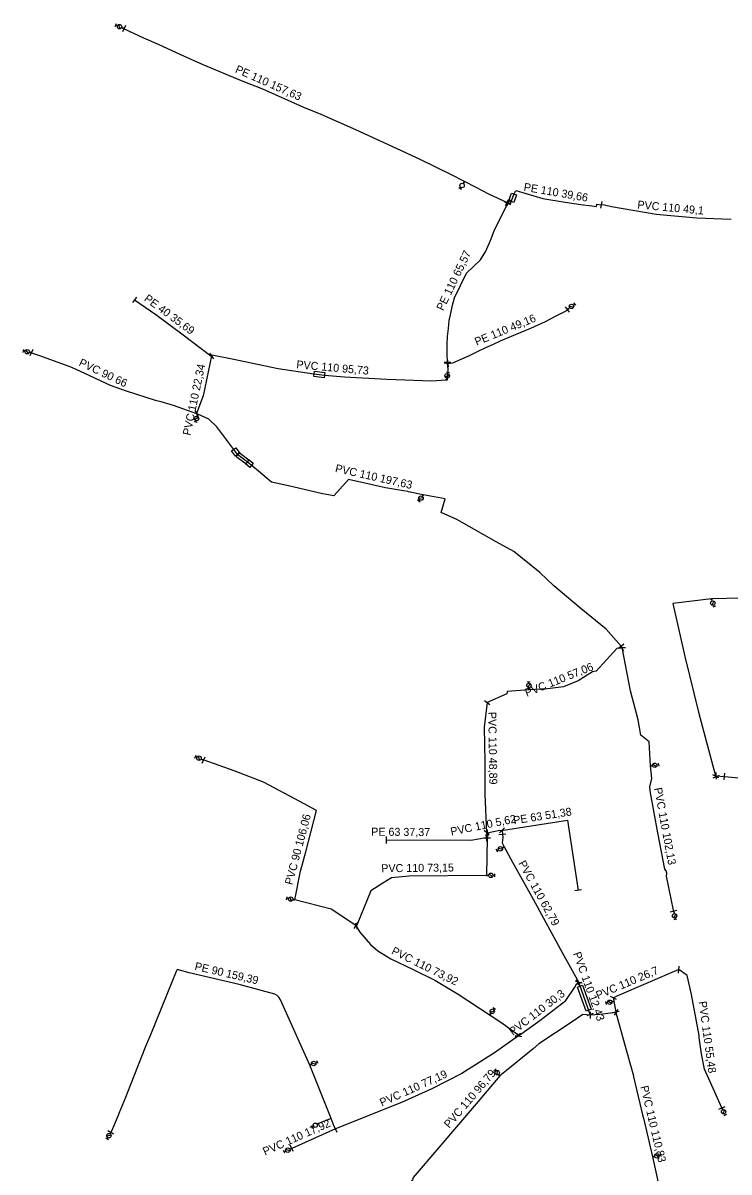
# Model space of a CAD drawing. Extents: x -736619 to -735426, y -1033122 to -1031044.
# Drawn here: x -736349.9 to -736085.4, y -1032291.7 to -1031861 of the extents above; entities that cross this region are included whole.
import ezdxf

# ---------------------------------------------------------------- set-up
doc = ezdxf.new("R2010")
doc.units = 0
for name, color, linetype in [('Vrstva 1', 7, 'Continuous'), ('Vrstva 17', 7, 'Continuous'), ('Vrstva 25', 7, 'Continuous'), ('Vrstva 27', 7, 'Continuous'), ('Vrstva 29', 7, 'Continuous'), ('Vrstva 63', 7, 'Continuous')]:
    doc.layers.add(name, color=color, linetype=linetype)

# ---------------------------------------------------------------- blocks, each defined once
blk = doc.blocks.new('100')
at = {"layer": 'Vrstva 1'}
blk.add_circle((0, 0), 0.127, dxfattribs=at)
blk = doc.blocks.new('133')
at = {"layer": 'Vrstva 1'}
for p, q in [((0.28, 0), (0, 0)), ((0.54, 0.58), (1.7, -0.58)), ((1.94, 0), (2.52, 0)), ((2.52, 0.58), (2.52, -0.58))]:
    blk.add_line(p, q, dxfattribs=at)
blk.add_circle((1.105, 0.003), 0.825, dxfattribs=at)
blk = doc.blocks.new('132')
at = {"layer": 'Vrstva 1'}
for p, q in [((0.3, 0), (0, 0)), ((1.96, 0), (2.52, 0)), ((2.52, 0.58), (2.52, -0.58))]:
    blk.add_line(p, q, dxfattribs=at)
blk.add_circle((1.13, -0.006), 0.825, dxfattribs=at)
blk = doc.blocks.new('147')
at = {"layer": 'Vrstva 1'}
blk.add_line((0, 1.27), (0, -1.27), dxfattribs=at)

msp = doc.modelspace()

# ---------------------------------------------------------------- linework, layer by layer
at = {"layer": 'Vrstva 17'}
for p, q in [((-736168.322, -1031928.384), (-736168.615, -1031928.284)), ((-736168.42, -1031928.571), (-736168.322, -1031928.384)), ((-736168.322, -1031928.384), (-736168.06, -1031928.485)), ((-736190.9, -1031988.615), (-736190.904, -1031988.283)), ((-736125.42, -1032095.1), (-736125.8, -1032094.64)), ((-736125.42, -1032095.1), (-736125.6, -1032095.31)), ((-736090.451, -1032143.226), (-736090.169, -1032143.164)), ((-736090.451, -1032143.226), (-736090.281, -1032143.568)), ((-736090.169, -1032143.164), (-736087.139, -1032143.448)), ((-736176.051, -1032166.446), (-736176.424, -1032166.463)), ((-736176.226, -1032164.522), (-736175.959, -1032164.508)), ((-736176.226, -1032164.522), (-736176.051, -1032166.446)), ((-736170.433, -1032163.629), (-736170.327, -1032165.199)), ((-736225.06, -1032199.49), (-736225.267, -1032199.35)), ((-736141.952, -1032220.805), (-736141.7, -1032220.64)), ((-736141.599, -1032220.922), (-736141.7, -1032220.64)), ((-736137.401, -1032232.618), (-736141.599, -1032220.922)), ((-736127.804, -1032231.644), (-736127.76, -1032231.89)), ((-736137.401, -1032232.618), (-736137.3, -1032232.9)), ((-736164.477, -1032240.514), (-736164.32, -1032240.71)), ((-736232.853, -1032275.556), (-736249.23, -1032282.84))]:
    msp.add_line(p, q, dxfattribs=at)
for points in [[(-736168.615, -1031928.284), (-736175.428, -1031925.208), (-736180.099, -1031922.637), (-736184.554, -1031920.463), (-736189.429, -1031917.854), (-736201.141, -1031912.125), (-736211.383, -1031907.462), (-736225.211, -1031900.986), (-736238.174, -1031895.312), (-736244.739, -1031892.631), (-736260.064, -1031885.853), (-736268.016, -1031882.681), (-736282.417, -1031876.63), (-736290.837, -1031872.981), (-736299.162, -1031869.075), (-736304.706, -1031866.65), (-736312.085, -1031863.138)], [(-736168.06, -1031928.485), (-736167.277, -1031928.78), (-736166.978, -1031927.91), (-736165.922, -1031925.088), (-736165.331, -1031923.741), (-736155.19, -1031926.729), (-736146.738, -1031928.197), (-736140.876, -1031929.078), (-736136.783, -1031929.493), (-736135.049, -1031929.742), (-736134.883, -1031928.861), (-736133.33, -1031929.133)], [(-736190.904, -1031988.283), (-736190.942, -1031985.057), (-736190.951, -1031981.538), (-736190.842, -1031978.488), (-736190.53, -1031975.494), (-736190.198, -1031972.508), (-736189.744, -1031970.431), (-736189.004, -1031966.813), (-736188.244, -1031963.975), (-736183.802, -1031954.754), (-736178.573, -1031949.714), (-736176.543, -1031946.492), (-736174.56, -1031941.881), (-736173.294, -1031938.547), (-736168.83, -1031929.627), (-736168.42, -1031928.571)], [(-736084.632, -1031934.715), (-736097.47, -1031934.21), (-736112.73, -1031932.78), (-736129.48, -1031929.89), (-736132.066, -1031929.318), (-736133.33, -1031929.133)], [(-735999.635, -1031957.835), (-736013.872, -1031954.746), (-736026.153, -1031952.022), (-736029.306, -1031968.97), (-736026.808, -1031979.076), (-736020.567, -1031991.616), (-736025.61, -1032047.78), (-736028.164, -1032073.797), (-736043.98, -1032076.566), (-736057.128, -1032076.327), (-736069.539, -1032076.342), (-736091.953, -1032076.886), (-736106.399, -1032078.551), (-736102.005, -1032098.49), (-736096.805, -1032119.288), (-736090.451, -1032143.226)], [(-736308.12, -1031964.78), (-736300.13, -1031970.32), (-736289.93, -1031977.86), (-736279.52, -1031985.72), (-736279.29, -1031985.78)], [(-736190.634, -1031988.619), (-736188.913, -1031988.38), (-736182.691, -1031985.622), (-736179.181, -1031983.934), (-736176.469, -1031982.61), (-736173.614, -1031981.368), (-736170.997, -1031980.172), (-736166.945, -1031978.393), (-736159.715, -1031975.426), (-736154.169, -1031972.842), (-736150.143, -1031970.748), (-736146.427, -1031968.846), (-736145.931, -1031968.445)], [(-736346.764, -1031984.582), (-736343.76, -1031985.62), (-736331.74, -1031990.06), (-736325.02, -1031993.1), (-736317.27, -1031996.77), (-736311.21, -1031998.92), (-736300.42, -1032002.39), (-736298.74, -1032002.78), (-736298.32, -1032002.9), (-736293.65, -1032004.31), (-736284.91, -1032007.34)], [(-736279.29, -1031985.78), (-736282.42, -1032000.76), (-736284.91, -1032007.34)], [(-736279.29, -1031985.78), (-736279.23, -1031985.37), (-736271.53, -1031986.92), (-736254.29, -1031990.53), (-736240.949, -1031992.509), (-736238.97, -1031992.8), (-736236.978, -1031992.976), (-736229.47, -1031993.64), (-736213.55, -1031994.49), (-736196.81, -1031995.09), (-736191.33, -1031994.79), (-736190.87, -1031994.78), (-736190.66, -1031990.78), (-736190.9, -1031988.615)], [(-736190.9, -1031988.615), (-736190.637, -1031988.619), (-736190.634, -1031988.619)], [(-736125.8, -1032094.64), (-736131.49, -1032088.22), (-736140.83, -1032080.59), (-736151.05, -1032071.92), (-736156.24, -1032067.01), (-736166.02, -1032059.09), (-736172.61, -1032055.44), (-736187.36, -1032047.13), (-736193.23, -1032044.47), (-736191.81, -1032039.35), (-736199.97, -1032037.81), (-736205.452, -1032036.695), (-736205.679, -1032036.649), (-736206.51, -1032036.48), (-736207.302, -1032036.344), (-736214.06, -1032035.18), (-736227.96, -1032032.06), (-736233.52, -1032038.21), (-736238.25, -1032037.41), (-736250.431, -1032034.55), (-736256.83, -1032033.06), (-736261.656, -1032029.029), (-736265.88, -1032025.5), (-736269.484, -1032022.811), (-736277.32, -1032012.34), (-736280.28, -1032009.46), (-736284.43, -1032007.6), (-736284.91, -1032007.34)], [(-736125.6, -1032095.31), (-736127.38, -1032095.44), (-736135.17, -1032103.99), (-736136.55, -1032104.2), (-736141.89, -1032107.56), (-736147.4, -1032109.78), (-736153.36, -1032110.59), (-736160.29, -1032110.9), (-736168.47, -1032111.61), (-736168.67, -1032112.42), (-736176.03, -1032115.71)], [(-736106.169, -1032193.855), (-736106.22, -1032193.61), (-736108.88, -1032180.76), (-736108.73, -1032179.74), (-736108.95, -1032178.86), (-736109.51, -1032178.13), (-736112.03, -1032164.58), (-736114.8, -1032149.57), (-736115.1, -1032147.38), (-736114.31, -1032144.17), (-736114.84, -1032139.51), (-736115.29, -1032130.5), (-736118.39, -1032127.95), (-736119.48, -1032122.16), (-736122.33, -1032111.38), (-736124.25, -1032101.65), (-736125.42, -1032095.1)], [(-736176.03, -1032115.71), (-736177.12, -1032124.95), (-736176.92, -1032137.98), (-736176.92, -1032150.05), (-736176.226, -1032164.522)], [(-736225.267, -1032199.35), (-736234.48, -1032193.13), (-736248.06, -1032189.74), (-736245.9, -1032178.98), (-736244.01, -1032171.68), (-736239.93, -1032156.24), (-736246.26, -1032152.77), (-736259.76, -1032145.62), (-736270.75, -1032141.28), (-736281.99, -1032137.38), (-736282.226, -1032137.298)], [(-736087.139, -1032143.448), (-736051.26, -1032146.807), (-735969.082, -1032157.753), (-735968.782, -1032157.944)], [(-736170.433, -1032163.629), (-736169.94, -1032163.621), (-736145.927, -1032159.879), (-736141.87, -1032186.147)], [(-736176.051, -1032166.446), (-736176.23, -1032180.53), (-736205.39, -1032180.84), (-736211.91, -1032181.46), (-736215.06, -1032183.4), (-736219.61, -1032186.35), (-736224.83, -1032199.15), (-736225.06, -1032199.49)], [(-736176.424, -1032166.463), (-736182.096, -1032167.491), (-736213.705, -1032167.265)], [(-736175.959, -1032164.508), (-736171.323, -1032163.563), (-736170.433, -1032163.629)], [(-736170.327, -1032165.199), (-736170.18, -1032166.37), (-736170.34, -1032168.35), (-736169.64, -1032169.8), (-736166.47, -1032175.568), (-736158.819, -1032189.491), (-736147.862, -1032209.427), (-736141.7, -1032220.64)], [(-736225.06, -1032199.49), (-736223.66, -1032201.77), (-736219.7, -1032206.48), (-736216.98, -1032208.86), (-736212.06, -1032211.75), (-736203.77, -1032215.75), (-736195.62, -1032219.79), (-736186.94, -1032225.01), (-736170.56, -1032235.73), (-736164.96, -1032239.91), (-736164.477, -1032240.514)], [(-736232.853, -1032275.556), (-736232.969, -1032275.402), (-736233.08, -1032275.097), (-736233.3, -1032274.668), (-736234.508, -1032271.624), (-736242.448, -1032251.664), (-736253.487, -1032227.194), (-736254.105, -1032226.208), (-736254.706, -1032225.532), (-736255.617, -1032225.043), (-736268.977, -1032221.453), (-736287.702, -1032217.085), (-736292.203, -1032215.804), (-736292.507, -1032216.574), (-736294.104, -1032220.494), (-736302.164, -1032240.308), (-736303.975, -1032244.7), (-736309.792, -1032259.315), (-736311.539, -1032263.791), (-736314.035, -1032269.822), (-736314.278, -1032270.487), (-736316.79, -1032276.359), (-736317.066, -1032276.876)], [(-736104.23, -1032215.85), (-736127.48, -1032225.76), (-736128.72, -1032226.47)], [(-736088.068, -1032267.654), (-736091.9, -1032259.24), (-736094.59, -1032253.15), (-736095.73, -1032247.4), (-736096.558, -1032241.323), (-736096.646, -1032240.531), (-736099.472, -1032225.118), (-736101.05, -1032218.03), (-736104.23, -1032215.85)], [(-736164.32, -1032240.71), (-736156.26, -1032234.88), (-736146.57, -1032227.39), (-736142.97, -1032222.1), (-736142.51, -1032221.17), (-736141.952, -1032220.805)], [(-736128.72, -1032226.47), (-736128.5, -1032227.75), (-736127.804, -1032231.644)], [(-736127.76, -1032231.89), (-736133.79, -1032232.69), (-736137.3, -1032232.9)], [(-736127.76, -1032231.89), (-736123.892, -1032245.969), (-736122.336, -1032251.633), (-736121.23, -1032255.66), (-736121.14, -1032256.039), (-736117.633, -1032270.788), (-736117.472, -1032271.47), (-736114.01, -1032286.03), (-736110.957, -1032300.183), (-736110.434, -1032302.61), (-736109.829, -1032305.414), (-736109.344, -1032307.663), (-736102.5, -1032339.39), (-736102.602, -1032339.755)], [(-736137.3, -1032232.9), (-736140.14, -1032232.68), (-736144.151, -1032235.36), (-736156.63, -1032243.7), (-736158.824, -1032245.508), (-736168.758, -1032253.69), (-736171.21, -1032255.71), (-736180.129, -1032266.149), (-736194.07, -1032282.467), (-736203.71, -1032293.75), (-736203.95, -1032294.59), (-736206.59, -1032298)], [(-736164.32, -1032240.71), (-736173.29, -1032247.09), (-736185.51, -1032254.79), (-736196.71, -1032260.52), (-736208.17, -1032265.69), (-736232.853, -1032275.556)]]:
    msp.add_lwpolyline(points, dxfattribs=at)
at = {"layer": 'Vrstva 27'}
for points in [[(-736167.913, -1031927.556), (-736166.859, -1031924.738), (-736164.985, -1031925.438), (-736166.04, -1031928.257), (-736167.913, -1031927.556)], [(-736240.759, -1031991.527), (-736236.862, -1031991.983), (-736237.094, -1031993.969), (-736240.991, -1031993.513), (-736240.759, -1031991.527)], [(-736270.17, -1032020.225), (-736268.683, -1032022.212), (-736270.285, -1032023.41), (-736271.771, -1032021.423), (-736270.17, -1032020.225)], [(-736268.886, -1032022.01), (-736265.282, -1032024.699), (-736266.478, -1032026.301), (-736270.082, -1032023.612), (-736268.886, -1032022.01)], [(-736265.239, -1032024.733), (-736263.682, -1032026.033), (-736264.965, -1032027.568), (-736266.521, -1032026.267), (-736265.239, -1032024.733)], [(-736140.261, -1032221.69), (-736137.021, -1032230.716), (-736138.904, -1032231.392), (-736142.143, -1032222.365), (-736140.261, -1032221.69)]]:
    msp.add_lwpolyline(points, dxfattribs=at)
at = {"layer": 'Vrstva 63'}
for p, q in [((-736160.29, -1032110.9), (-736160.312, -1032110.4)), ((-736282.226, -1032137.298), (-736282.935, -1032137.052)), ((-736114.84, -1032139.51), (-736114.343, -1032139.453)), ((-736169.64, -1032169.8), (-736170.078, -1032170.041)), ((-736176.23, -1032180.53), (-736175.747, -1032180.522)), ((-736248.06, -1032189.74), (-736248.55, -1032189.642)), ((-736128.5, -1032227.75), (-736128.993, -1032227.835)), ((-736174.995, -1032232.828), (-736174.726, -1032232.421)), ((-736171.21, -1032255.71), (-736171.528, -1032255.324)), ((-736088.068, -1032267.654), (-736087.86, -1032268.11)), ((-736317.066, -1032276.876), (-736317.188, -1032277.107)), ((-736249.23, -1032282.84), (-736249.691, -1032283.033)), ((-736114.01, -1032286.03), (-736113.524, -1032285.914))]:
    msp.add_line(p, q, dxfattribs=at)
for points in [[(-736312.085, -1031863.138), (-736312.452, -1031862.955), (-736312.755, -1031862.841)], [(-736184.554, -1031920.463), (-736184.671, -1031920.699), (-736184.814, -1031920.95)], [(-736145.931, -1031968.445), (-736145.573, -1031968.154), (-736145.279, -1031967.924)], [(-736346.764, -1031984.582), (-736347.06, -1031984.48), (-736347.26, -1031984.45)], [(-736191.33, -1031994.79), (-736191.28, -1031994.58), (-736191.23, -1031994.34)], [(-736284.43, -1032007.6), (-736284.57, -1032007.92), (-736284.64, -1032008.22)], [(-736199.97, -1032037.81), (-736200.02, -1032037.97), (-736200.17, -1032038.19)], [(-736091.953, -1032076.886), (-736091.946, -1032077.116), (-736091.842, -1032077.388)], [(-736106.169, -1032193.855), (-736106.118, -1032194.1), (-736106.017, -1032194.589)], [(-736242.448, -1032251.664), (-736242.148, -1032251.545), (-736242.032, -1032251.501)], [(-736234.508, -1032271.624), (-736239.21, -1032273.485), (-736239.443, -1032273.623)]]:
    msp.add_lwpolyline(points, dxfattribs=at)

# ---------------------------------------------------------------- block references
at = {"layer": 'Vrstva 25'}
for name, p, xscale, yscale, rotation in [('133', (-736312.755, -1031862.841), 1.0275072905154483, 1.027507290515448, 155.31089431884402), ('132', (-736184.814, -1031920.95), 0.9999999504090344, 0.9999999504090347, -121.00000158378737), ('133', (-736145.279, -1031967.924), 0.9999999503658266, 0.9999999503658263, 37.999999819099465), ('133', (-736347.26, -1031984.45), 1.00837761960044, 1.00837761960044, 168.3736213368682), ('133', (-736191.23, -1031994.34), 0.999999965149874, 0.9999999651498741, 77.9999999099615), ('133', (-736284.64, -1032008.22), 0.9999999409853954, 0.9999999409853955, -104.00000032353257), ('133', (-736200.17, -1032038.19), 0.9999999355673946, 0.9999999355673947, -124.99999939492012), ('133', (-736091.842, -1032077.388), 0.9999999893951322, 0.9999999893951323, -70.00000094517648), ('133', (-736160.312, -1032110.4), 0.9999999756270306, 0.9999999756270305, 93.00000001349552), ('133', (-736282.935, -1032137.052), 1.0316957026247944, 1.0316957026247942, 156.4154111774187), ('133', (-736114.343, -1032139.453), 1.0098116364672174, 1.0098116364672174, 10.610300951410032), ('133', (-736170.078, -1032170.041), 1.0072562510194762, 1.0072562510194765, -151.23333635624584), ('133', (-736175.747, -1032180.522), 0.9999999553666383, 0.9999999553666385, 1.000000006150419), ('133', (-736248.55, -1032189.642), 1.0060666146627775, 1.0060666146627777, 167.3452647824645), ('133', (-736106.017, -1032194.589), 0.9999999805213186, 0.9999999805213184, -79.00000058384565), ('133', (-736128.993, -1032227.835), 1.00837761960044, 1.00837761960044, -168.3736213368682), ('133', (-736174.726, -1032232.421), 0.9999999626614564, 0.9999999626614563, 57.00000159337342), ('133', (-736242.032, -1032251.501), 1.0275072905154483, 1.027507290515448, 24.689105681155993), ('133', (-736171.528, -1032255.324), 0.9999999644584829, 0.999999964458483, 129.00000106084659), ('133', (-736087.86, -1032268.11), 0.9999999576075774, 0.9999999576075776, -66.99999911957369), ('132', (-736239.443, -1032273.623), 0.9999999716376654, 0.9999999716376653, -150.00000103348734), ('133', (-736317.188, -1032277.107), 0.999999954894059, 0.9999999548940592, -119.00000058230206), ('133', (-736249.691, -1032283.033), 1.025136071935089, 1.0251360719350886, -154.74924162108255), ('133', (-736113.524, -1032285.914), 1.0028916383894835, 1.0028916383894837, 13.697207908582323)]:
    msp.add_blockref(name, p, dxfattribs=dict(at, xscale=xscale, yscale=yscale, rotation=rotation))
at = {"layer": 'Vrstva 29'}
for p, xscale, yscale, rotation in [((-736312.085, -1031863.138), 1.0138864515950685, 1.0138864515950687, -27.5653151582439), ((-736168.42, -1031928.571), 0.9999999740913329, 0.9999999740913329, 65.99999939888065), ((-736168.615, -1031928.284), 1.025136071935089, 1.0251360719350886, 154.74924162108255), ((-736168.322, -1031928.384), 1.0275072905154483, 1.027507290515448, -24.689105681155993), ((-736168.06, -1031928.485), 1.025136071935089, 1.0251360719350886, -25.250758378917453), ((-736133.33, -1031929.133), 1.0073309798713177, 1.007330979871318, -12.138907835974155), ((-736308.12, -1031964.78), 0.9999999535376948, 0.9999999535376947, -36.000001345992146), ((-736145.931, -1031968.445), 0.9999999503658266, 0.9999999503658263, -142.00000018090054), ((-736346.764, -1031984.582), 1.0296949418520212, 1.0296949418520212, -24.133789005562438), ((-736279.29, -1031985.78), 0.9999999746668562, 0.999999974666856, 34.00000045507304), ((-736190.9, -1031988.615), 0.9999999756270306, 0.9999999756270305, -86.99999998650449), ((-736190.634, -1031988.619), 1.0002788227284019, 1.0002788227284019, -176.70930040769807), ((-736284.91, -1032007.34), 1.0169561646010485, 1.0169561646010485, 26.97601647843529), ((-736125.8, -1032094.64), 0.9999999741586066, 0.9999999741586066, -50.000001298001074), ((-736125.6, -1032095.31), 1.0106517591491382, 1.010651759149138, 28.162115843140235), ((-736125.42, -1032095.1), 0.9999999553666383, 0.9999999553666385, 88.99999999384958), ((-736176.03, -1032115.71), 0.9999999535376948, 0.9999999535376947, 53.99999865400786), ((-736282.226, -1032137.298), 1.0316957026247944, 1.0316957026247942, 156.4154111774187), ((-736090.451, -1032143.226), 0.9999999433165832, 0.999999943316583, 64.0000000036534), ((-736090.281, -1032143.568), 0.9999999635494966, 0.9999999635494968, -65.00000039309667), ((-736090.169, -1032143.164), 1.0002788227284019, 1.0002788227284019, -176.70930040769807), ((-736087.139, -1032143.448), 1.0018264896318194, 1.0018264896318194, 173.9218730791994), ((-736170.433, -1032163.629), 0.9999999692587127, 0.9999999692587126, -46.00000080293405), ((-736176.051, -1032166.446), 0.9999999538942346, 0.9999999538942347, 92.0000000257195), ((-736176.226, -1032164.522), 0.9999999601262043, 0.9999999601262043, -131.99999877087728), ((-736176.424, -1032166.463), 1.0011216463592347, 1.0011216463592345, 6.5826102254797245), ((-736175.959, -1032164.508), 1.0098116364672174, 1.0098116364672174, 10.610300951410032), ((-736170.327, -1032165.199), 0.9999999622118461, 0.999999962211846, -85.0000001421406), ((-736141.87, -1032186.147), 0.9999999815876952, 0.9999999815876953, -82.0000004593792), ((-736106.169, -1032193.855), 0.999999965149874, 0.9999999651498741, 102.0000000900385), ((-736225.267, -1032199.35), 0.9999999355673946, 0.9999999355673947, -34.99999939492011), ((-736225.06, -1032199.49), 1.0060666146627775, 1.0060666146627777, 12.654735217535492), ((-736104.23, -1032215.85), 1.0011216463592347, 1.0011216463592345, 173.41738977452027), ((-736141.7, -1032220.64), 0.999999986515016, 0.9999999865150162, -105.00000012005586), ((-736141.599, -1032220.922), 0.9999999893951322, 0.9999999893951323, 109.99999905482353), ((-736141.952, -1032220.805), 0.9999999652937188, 0.9999999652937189, -148.0000026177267), ((-736128.72, -1032226.47), 0.9999999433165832, 0.999999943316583, -115.9999999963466), ((-736127.804, -1032231.644), 0.9999999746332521, 0.9999999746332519, 99.99999944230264), ((-736127.76, -1032231.89), 0.9999999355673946, 0.9999999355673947, -34.99999939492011), ((-736137.401, -1032232.618), 0.9999999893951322, 0.9999999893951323, 109.99999905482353), ((-736164.32, -1032240.71), 0.9999999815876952, 0.9999999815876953, 82.0000004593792), ((-736164.477, -1032240.514), 0.9999999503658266, 0.9999999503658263, -52.00000018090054), ((-736088.068, -1032267.654), 0.9999999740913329, 0.9999999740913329, 114.00000060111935), ((-736232.853, -1032275.556), 1.022584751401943, 1.022584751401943, 25.818974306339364), ((-736317.066, -1032276.876), 0.999999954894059, 0.9999999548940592, -119.00000058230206), ((-736249.23, -1032282.84), 1.025136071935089, 1.0251360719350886, -154.74924162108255)]:
    msp.add_blockref('147', p, dxfattribs=dict(at, xscale=xscale, yscale=yscale, rotation=rotation))
for p, rotation in [((-736190.904, -1031988.283), -90), ((-736213.705, -1032167.265), 180), ((-736137.3, -1032232.9), 180)]:
    msp.add_blockref('147', p, dxfattribs=dict(at, rotation=rotation))
at = {"layer": 'Vrstva 63'}
for p, xscale, yscale, rotation in [((-736312.452, -1031862.955), 1.025136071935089, 1.0251360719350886, -25.250758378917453), ((-736184.671, -1031920.7), 0.9999999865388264, 0.9999999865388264, 59.99999955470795), ((-736145.573, -1031968.154), 0.9999999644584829, 0.999999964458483, 39.000001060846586), ((-736347.06, -1031984.48), 0.999999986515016, 0.9999999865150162, -15.000000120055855), ((-736191.28, -1031994.58), 0.9999999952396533, 0.9999999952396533, 77.00000056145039), ((-736284.57, -1032007.92), 0.9999999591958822, 0.9999999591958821, 72.00000054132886), ((-736200.02, -1032037.97), 0.9999999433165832, 0.999999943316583, 64.0000000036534), ((-736091.946, -1032077.116), 0.9999999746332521, 0.9999999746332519, -80.00000055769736), ((-736160.301, -1032110.65), 0.9999999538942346, 0.9999999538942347, -87.9999999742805), ((-736282.462, -1032137.216), 1.0296949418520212, 1.0296949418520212, -24.133789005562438), ((-736114.592, -1032139.482), 1.0098116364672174, 1.0098116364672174, 10.610300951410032), ((-736169.859, -1032169.92), 1.0037041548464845, 1.0037041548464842, 29.379208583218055), ((-736175.991, -1032180.526), 0.9999999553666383, 0.9999999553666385, 1.000000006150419), ((-736248.305, -1032189.691), 1.0045862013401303, 1.00458620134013, -13.17409066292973), ((-736106.118, -1032194.1), 0.9999999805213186, 0.9999999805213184, -79.00000058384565), ((-736128.746, -1032227.792), 1.0073309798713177, 1.007330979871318, 12.138907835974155), ((-736174.857, -1032232.619), 0.9999999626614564, 0.9999999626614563, 57.00000159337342), ((-736242.148, -1032251.545), 1.0275072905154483, 1.027507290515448, 24.689105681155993), ((-736171.369, -1032255.517), 0.9999999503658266, 0.9999999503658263, -52.00000018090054), ((-736087.964, -1032267.882), 0.9999999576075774, 0.9999999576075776, -66.99999911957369), ((-736239.21, -1032273.485), 1.0138864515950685, 1.0138864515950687, 27.5653151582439), ((-736249.46, -1032282.936), 1.022584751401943, 1.022584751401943, 25.818974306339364), ((-736113.767, -1032285.972), 1.0028916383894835, 1.0028916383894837, 13.697207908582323)]:
    msp.add_blockref('100', p, dxfattribs=dict(at, xscale=xscale, yscale=yscale, rotation=rotation))

# ---------------------------------------------------------------- texts
for s, height, rotation, p in [('PE 110 157,63', 2.99999, 336.14, (-736270.667, -1031879.41)), ('PE 110 39,66', 2.99999, 350.15, (-736162.491, -1031923.837)), ('PVC 110 49,1', 2.99999, 354.65, (-736119.834, -1031930.508)), ('PE 110 65,57', 2.99999, 64.28, (-736192.49, -1031969.105)), ('PE 40 35,69', 2.99999, 323.53, (-736304.787, -1031964.888)), ('PE 110 49,16', 2.99999, 22.31, (-736179.95, -1031981.992)), ('PVC 90 66', 3, 334.66, (-736329.248, -1031989.327)), ('PVC 110 22,34', 2.99999, 78.2, (-736287.194, -1032015.791)), ('PVC 110 95,73', 2.99999, 354.95, (-736247.584, -1031990.433)), ('PVC 110 197,63', 2.99999, 347.35, (-736233.164, -1032029.252)), ('PVC 110 57,06', 2.99999, 21.94, (-736161.165, -1032113.599)), ('PVC 110 48,89', 2.99999, 270.88, (-736175.607, -1032119.261)), ('PVC 110 102,13', 2.99999, 280.54, (-736113.512, -1032147.867)), ('PVC 90 106,06', 2.99999, 75.2, (-736248.995, -1032184.284)), ('PVC 110 5,62', 2.99999, 11.52, (-736189.429, -1032165.62)), ('PE 63 51,38', 2.99999, 8.86, (-736165.992, -1032161.387)), ('PE 63 37,37', 2.99999, 359.59, (-736219.465, -1032165.623)), ('PVC 110 73,15', 2.99999, 0.61, (-736215.664, -1032179.349)), ('PVC 110 62,79', 2.99999, 298.79, (-736164.437, -1032175.944)), ('PVC 110 73,92', 2.99999, 333.63, (-736212.151, -1032209.809)), ('PVC 110 12,43', 2.99999, 289.74, (-736143.885, -1032209.809)), ('PE 90 159,39', 2.99999, 346.87, (-736285.802, -1032215.885)), ('PVC 110 26,7', 2.99999, 23.09, (-736134.509, -1032227.018)), ('PVC 110 30,3', 2.99999, 37.7, (-736166.367, -1032240.67)), ('PVC 110 55,48', 2.99999, 277.76, (-736096.778, -1032227.861)), ('PVC 110 77,19', 2.99999, 24.28, (-736215.453, -1032267.219)), ('PVC 110 96,79', 2.99999, 49.49, (-736190.218, -1032275.494)), ('PVC 110 110,83', 2.99999, 283.38, (-736118.625, -1032259.709)), ('PVC 110 17,92', 2.99999, 23.98, (-736259.262, -1032285.551))]:
    msp.add_text(s, height=height, rotation=rotation, dxfattribs=at).set_placement(p)

doc.saveas('drawing.dxf')
